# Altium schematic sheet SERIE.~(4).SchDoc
size A4
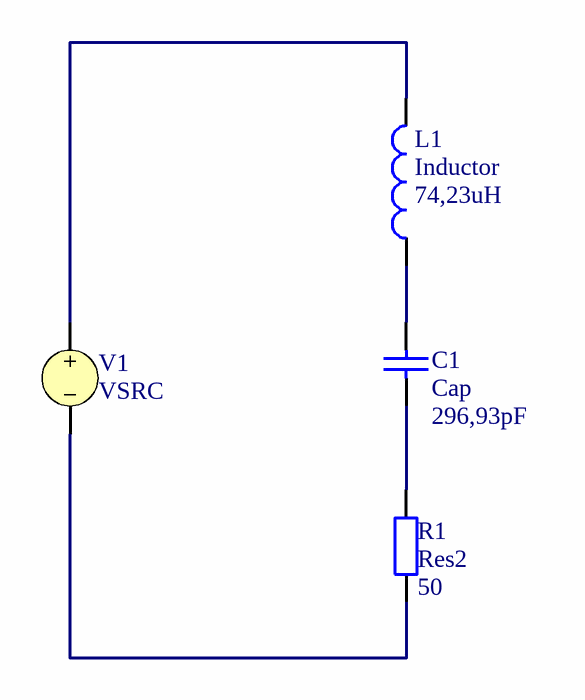
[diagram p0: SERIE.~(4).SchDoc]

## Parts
C1  Cap  value 296,93pF  [RAD-0.3]
L1  Inductor  value 74,23uH  [0402-A]
R1  Res2  value 50  [AXIAL-0.4]
V1  VSRC

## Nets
NetC1_1: C1.1 L1.1
NetC1_2: C1.2 R1.2
NetL1_2: L1.2 V1.1
NetR1_1: R1.1 V1.2

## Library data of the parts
C1 = Cap: Capacitor
L1 = Inductor: Code_IEC: 1005
R1 = Res2: Resistor
V1 = VSRC: Voltage Source; Note: PCB Footprint - Not required; Value: 10mV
